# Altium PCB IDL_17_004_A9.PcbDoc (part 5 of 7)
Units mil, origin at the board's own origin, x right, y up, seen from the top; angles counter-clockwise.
Board outline 9493.25 x 7199.68 mil, 6 copper layers (Top Layer - SIG1, Layer 2 - GND1, Layer 3 - PWR1, Layer 4 - PWR2, Layer 5 - GND2, Bottom Layer - SIG2), stack 60.592 mil thick; 403 components, 274 nets, 1834 pads, 1849 vias.
Unrouted connection lines stored in the file: 1.
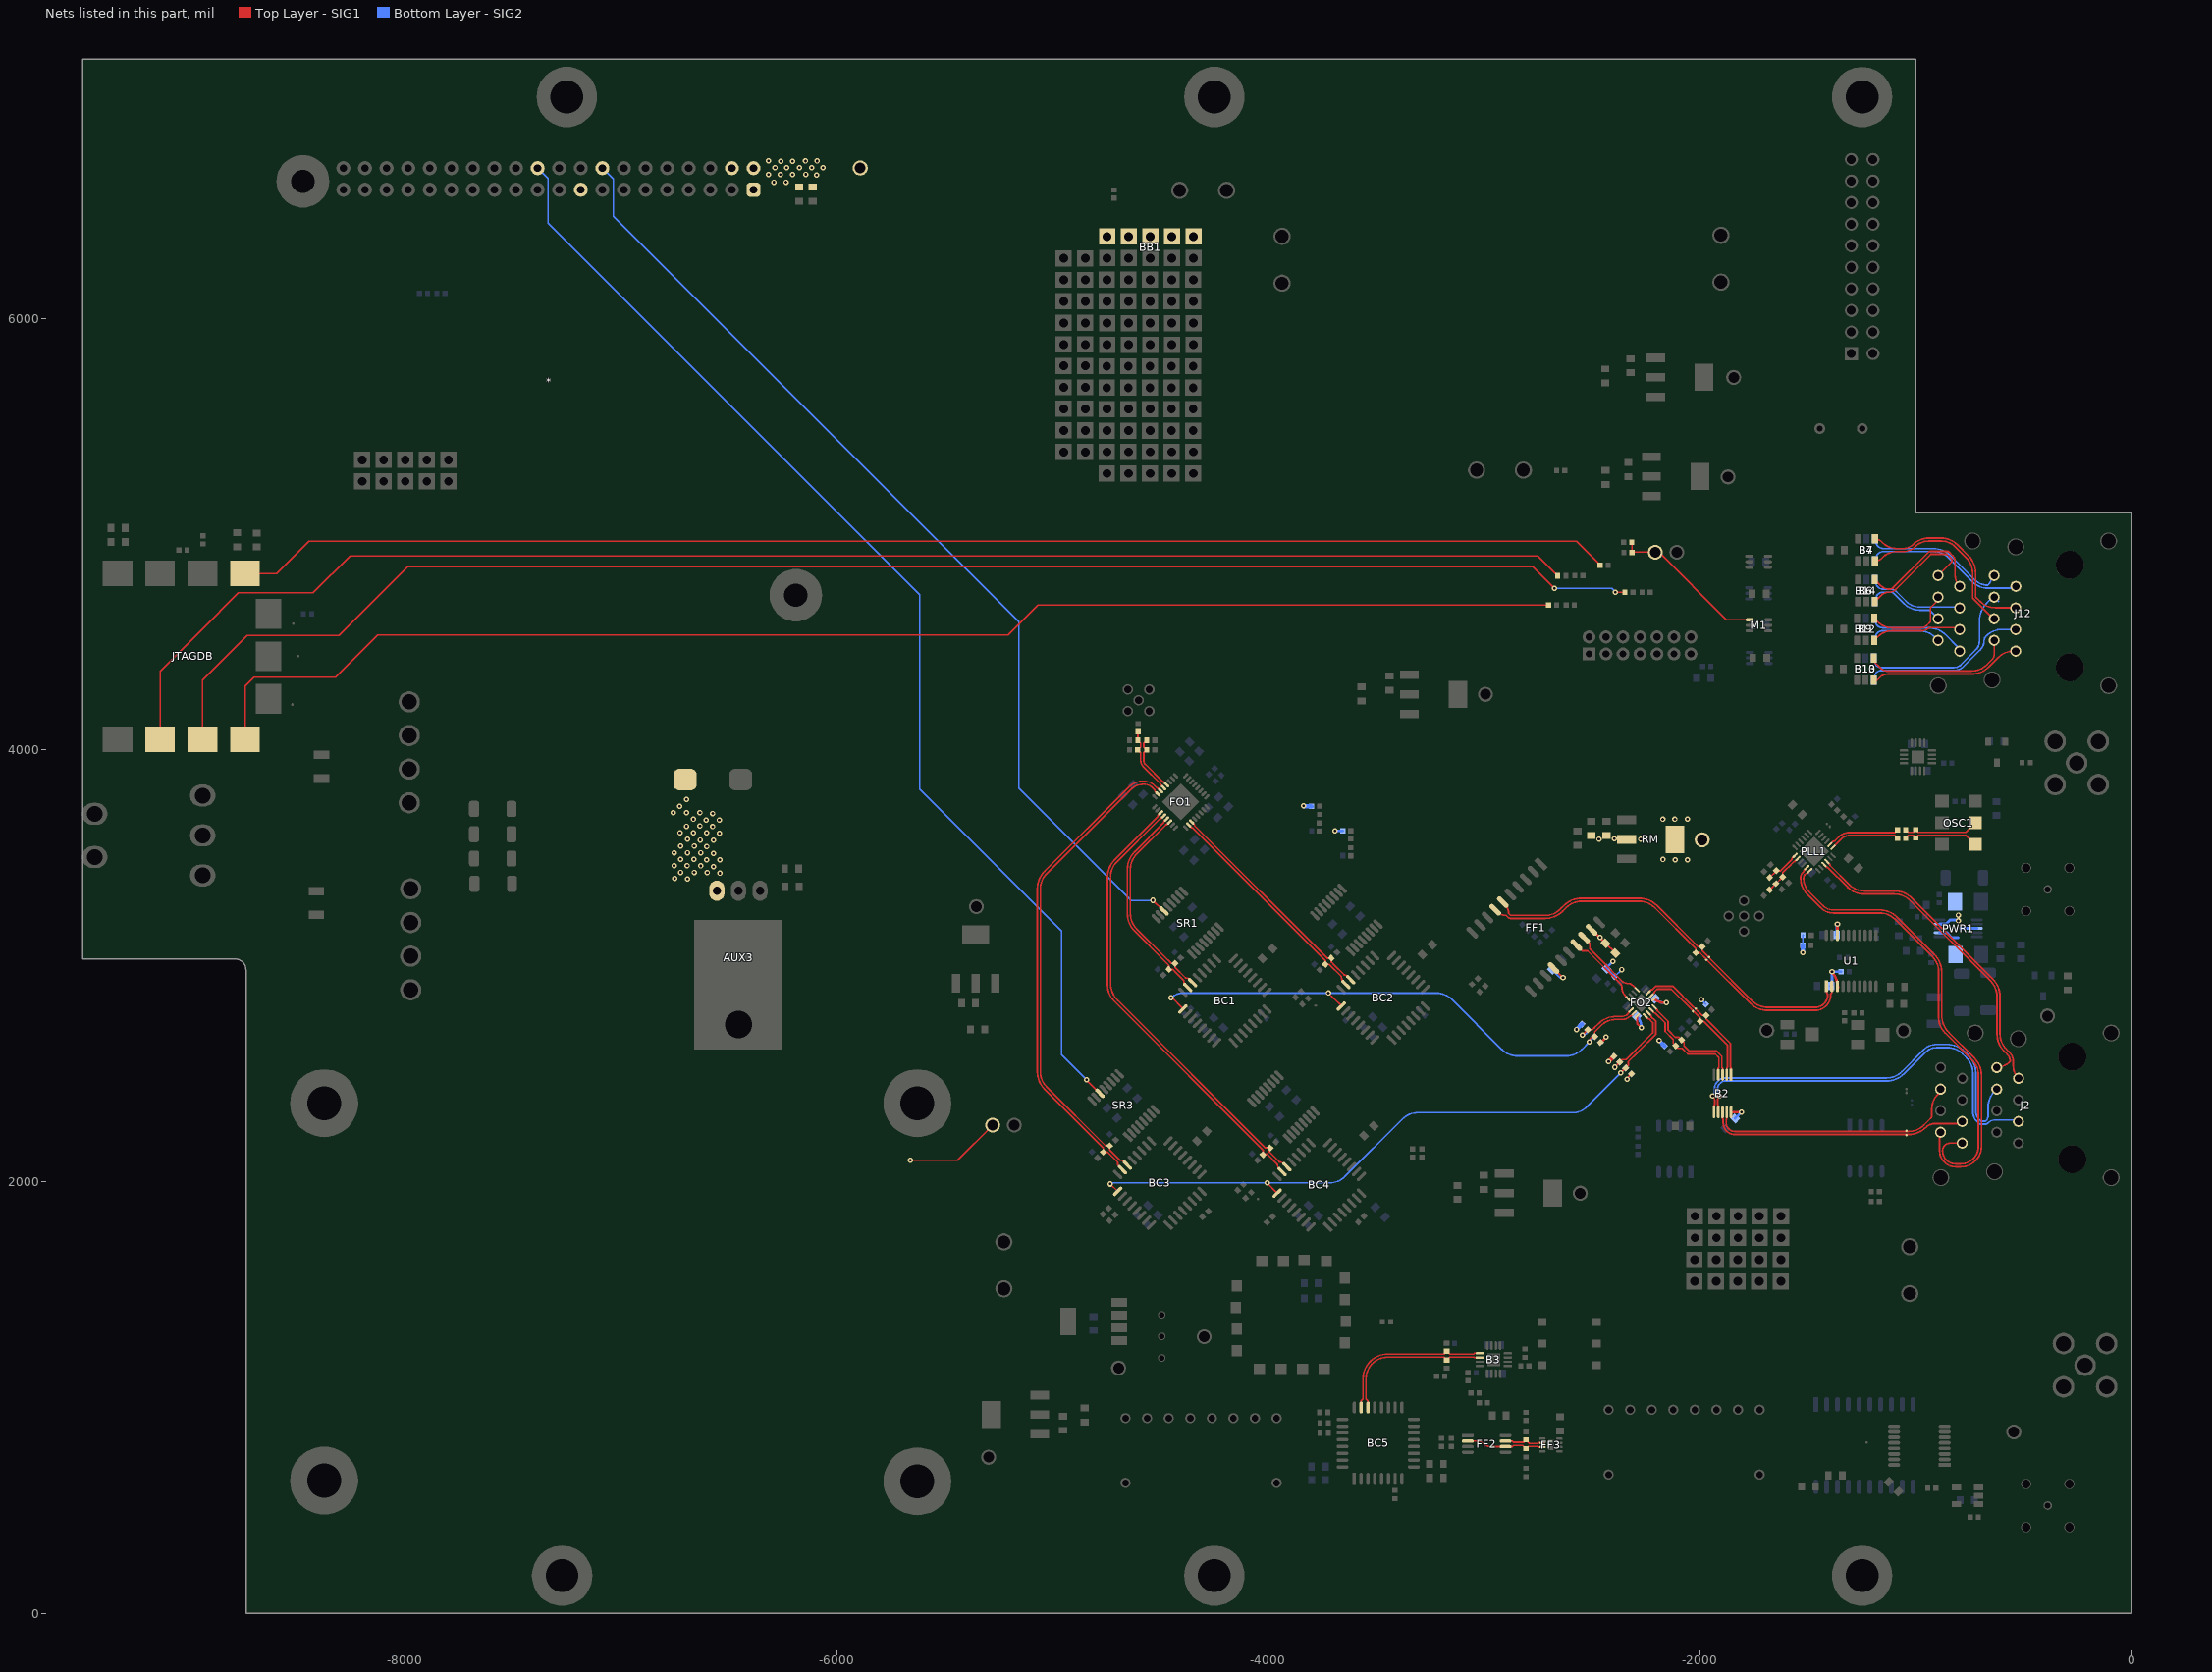
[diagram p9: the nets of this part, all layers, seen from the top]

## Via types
v1: diameter 25, hole 12, Top Layer - SIG1 to Bottom Layer - SIG2, tented both sides, 1502 vias
v2: diameter 25, hole 12, Top Layer - SIG1 to Bottom Layer - SIG2, 184 vias
v3: diameter 25.59, hole 11.81, Top Layer - SIG1 to Bottom Layer - SIG2, tented both sides, 163 vias

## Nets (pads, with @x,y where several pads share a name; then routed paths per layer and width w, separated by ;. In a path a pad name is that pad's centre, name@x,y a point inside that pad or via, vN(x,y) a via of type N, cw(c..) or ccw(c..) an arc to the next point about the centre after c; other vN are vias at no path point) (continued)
RFCLK2-1_N: BC2.23 FO1.26 R60.1 | length 1051.9
  Top Layer - SIG1 w8: FO1.26@-4368.92,3652.85 -4358.33,3642.26 ccw(c-4351.47,3649.12) -4351.47,3639.42 -3736.35,3024.3 R60.1@-3736.35,3007.45 -3718.19,3007.45 -3662.97,2952.24 ccw(c-3623.18,2952.24) -3651.32,2924.1 BC2.23@-3640.66,2913.44
RFCLK2-1_P: BC2.22 FO1.27 R59.1 | length 1051.2
  Top Layer - SIG1 w8: FO1.27@-4355,3666.77 -4344.41,3656.18 cw(c-4351.27,3649.32) -4341.57,3649.32 -3727.9,3035.65 R59.1@-3708.43,3035.65 -3708.43,3017.5 -3695.6,3004.66 -3648.96,2958.03 cw(c-3648.96,2938.08) -3634.86,2952.18 BC2.22@-3618.39,2935.71
RFCLK3-1_N: BC1.23 FO1.21 R58.1 | length 973.2
  Top Layer - SIG1 w8: -4474.75,3016.48 -4461.02,3002.75 R58.1@-4461.02,2983.32 -4443.09,2983.32 -4430.42,2970.65 -4391.82,2932.05 ccw(c-4367.27,2932.05) -4384.63,2914.69 BC1.23@-4369.5,2899.56 ; -4474.76,3016.48 -4619.86,3161.59 cw(c-4539.25,3242.2) -4653.25,3242.2 -4653.25,3447.62 cw(c-4539.25,3447.62) -4619.86,3528.23 -4484.85,3663.24 cw(c-4475.14,3663.24) -4482.01,3670.1 FO1.21@-4471.41,3680.69
RFCLK3-1_P: BC1.22 FO1.22 R57.1 | length 951.2
  Top Layer - SIG1 w8: FO1.22@-4457.49,3666.77 -4468.09,3656.18 cw(c-4474.95,3663.04) -4474.95,3653.34 -4609.96,3518.33 ccw(c-4539.25,3447.62) -4639.25,3447.62 -4639.25,3242.2 ccw(c-4539.25,3242.2) -4609.96,3171.49 -4485.25,3046.77 -4449.51,3011.03 R57.1@-4433.08,3011.03 -4433.08,2993.11 -4384.12,2944.15 cw(c-4384.12,2908.96) -4359.25,2933.85 BC1.22@-4347.23,2921.83
RFCLK4-1_N: BC4.23 FO1.19 R77.1 | length 2103.6
  Top Layer - SIG1 w8: FO1.19@-4499.25,3708.53 -4509.84,3697.94 ccw(c-4502.98,3691.07) -4512.69,3691.07 -4711.86,3491.9 ccw(c-4631.25,3411.29) -4745.25,3411.29 -4745.25,2909.28 ccw(c-4645.25,2909.28) -4715.96,2838.57 -4024.94,2147.55 R77.1@-4024.94,2125.33 -4022.03,2128.24 R77.1@-4021.39,2128.24 ; R77.1@-4020.85,2127.7 R77.1@-4021.39,2128.24 ; BC4.23@-3936.75,2047.06 -3950.32,2060.63 cw(c-3929.2,2081.75) -3959.07,2081.75 -4005.56,2128.24 R77.1@-4021.39,2128.24
RFCLK4-1_P: BC4.22 FO1.20 R76.1 | length 2075.1
  Top Layer - SIG1 w8: -4731.25,3407.27 -4731.25,2920.88 ccw(c-4617.25,2920.88) -4697.86,2840.27 -4014.72,2157.13 R76.1@-3992.5,2157.13 -3994.81,2154.82 -3994.81,2137.29 -3949.17,2091.65 cw(c-3949.17,2061.78) -3928.05,2082.9 BC4.22@-3914.48,2069.33 ; -4731.25,3411.29 cw(c-4631.25,3411.29) -4701.96,3482 -4502.79,3681.17 ccw(c-4502.79,3690.88) -4495.93,3684.02 FO1.20@-4485.33,3694.61
RFCLK5-1_N: BC3.23 FO1.14 R75.1 | length 2282.8
  Top Layer - SIG1 w8: BC3.23@-4675.61,2055.55 -4697.93,2077.87 -4697.93,2090.24 -4744.76,2137.07 R75.1@-4764.71,2137.07 -4764.71,2157.01 -5036.89,2429.19 cw(c-4956.28,2509.8) -5070.28,2509.8 -5070.28,3357.4 cw(c-4956.28,3357.4) -5036.89,3438.01 -4648.83,3826.07 cw(c-4578.12,3755.36) -4578.12,3855.36 -4576.41,3855.36 cw(c-4576.41,3785.83) -4527.25,3835 -4516.71,3824.46 cw(c-4516.71,3814.75) -4509.84,3821.61 FO1.14@-4499.25,3811.02
RFCLK5-1_P: BC3.22 FO1.15 R74.1 | length 2238.6
  Top Layer - SIG1 w8: BC3.22@-4653.34,2077.82 -4675.66,2100.14 -4688.03,2100.14 -4734.87,2146.98 R74.1@-4734.87,2166.91 -4754.81,2166.91 -5026.99,2439.09 cw(c-4956.28,2509.8) -5056.28,2509.8 -5056.28,3357.4 cw(c-4956.28,3357.4) -5026.99,3428.11 -4640.14,3814.96 cw(c-4576.41,3751.24) -4576.41,3841.36 cw(c-4576.41,3785.83) -4537.15,3825.1 -4526.61,3814.56 ccw(c-4516.9,3814.56) -4523.76,3807.69 FO1.15@-4513.17,3797.1
RFCLK6_N: FO1.12 R9.1 R11.2 | length 269.4
  Top Layer - SIG1 w8: R11.2@-4563.89,4044.99 -4577.63,4031.25 -4577.63,4012.92 -4569.71,4004.99 -4567.99,4004.99 R9.1@-4563.99,4000.99 -4577.63,3987.35 -4577.63,3951.99 ccw(c-4551.24,3951.99) -4569.9,3933.33 -4488.87,3852.29 -4484.85,3852.29 FO1.12@-4471.41,3838.86
RFCLK6_P: C22.1 FO1.13 R10.1 R12.2 | length 321.6
  Top Layer - SIG1 w8: R12.2@-4605.28,4000.59 R12.2@-4605.28,4001.15 ; R12.2@-4605.27,4000.59 cw(c-4565.2,4001.15) R12.2@-4605.28,4001.15 ; C22.1@-4604.38,4084.88 -4605.09,4084.16 R10.1@-4605.09,4044.99 -4591.63,4031.53 -4591.63,4012.92 -4599.4,4005.15 -4601.28,4005.15 R12.2@-4605.28,4001.15 ; FO1.13@-4485.33,3824.94 -4498.77,3838.37 -4498.77,3842.39 -4579.8,3923.43 cw(c-4551.24,3951.99) -4591.63,3951.99 -4591.63,3987.51 R12.2@-4605.28,4001.15
RFOUT0_N: J2.8 PLL1.21 | length 1456
  Top Layer - SIG1 w8: PLL1.21@-1426.23,3469.34 -1415.11,3458.22 ccw(c-1408.24,3465.08) -1408.24,3455.38 -1315.98,3363.11 ccw(c-1243.28,3435.81) -1243.28,3333 -1099.42,3333 cw(c-1099.42,3233) -1028.71,3303.71 -654.29,2929.29 cw(c-725,2858.58) -625,2858.58 -625,2684.94 ccw(c-511,2684.94) -591.61,2604.33 -577.25,2589.97 cw(c-610.09,2557.12) -563.64,2557.12 -564.13,2556.63 cw(c-625,2617.49) -625,2531.41 cw(c-628.41,2531.41) J2.8@-626,2529
RFOUT0_P: J2.7 PLL1.22 | length 1480.1
  Top Layer - SIG1 w8: PLL1.22@-1412.31,3483.26 -1401.19,3472.14 cw(c-1408.05,3465.28) -1398.34,3465.28 -1308.92,3375.86 ccw(c-1239.26,3445.52) -1239.26,3347 -1099.42,3347 cw(c-1099.42,3233) -1018.81,3313.61 -644.39,2939.19 cw(c-725,2858.58) -611,2858.58 -611,2684.94 ccw(c-511,2684.94) -581.71,2614.23 -567.35,2599.87 cw(c-610.09,2557.12) -549.64,2557.12 -549.64,2537.02 ccw(c-467.6,2537.02) J2.7@-525.61,2479.01
RFOUT1_N: J2.16 PLL1.17 | length 2145.7
  Top Layer - SIG1 w8: PLL1.17@-1505.57,3455.42 -1516.69,3444.3 ccw(c-1509.83,3437.44) -1519.53,3437.44 -1524.44,3432.53 ccw(c-1500.11,3408.21) -1534.51,3408.21 -1534.51,3403.57 ccw(c-1436.01,3403.57) -1505.67,3333.92 -1440.41,3268.67 ccw(c-1383.28,3325.8) -1383.28,3245 -1168.03,3245 cw(c-1168.03,3145) -1097.32,3215.71 -924.54,3042.93 cw(c-995.25,2972.22) -895.25,2972.22 -895.25,2760.67 ccw(c-795.25,2760.67) -865.96,2689.96 -740.29,2564.29 cw(c-811,2493.58) -711,2493.58 -711,2164 cw(c-792,2164) -792,2083 -816,2083 cw(c-816,2144) -877,2144 cw(c-841.99,2144) -841.99,2179.01 J2.16@-786.01,2179.01
RFOUT1_P: J2.15 PLL1.18 | length 2154.4
  Top Layer - SIG1 w8: PLL1.18@-1491.65,3441.5 -1502.77,3430.38 cw(c-1509.63,3437.24) -1509.63,3427.54 -1514.54,3422.63 ccw(c-1500.11,3408.21) -1520.51,3408.21 -1520.51,3403.57 ccw(c-1436.01,3403.57) -1495.76,3343.82 -1430.51,3278.57 ccw(c-1383.28,3325.8) -1383.28,3259 -1168.03,3259 cw(c-1168.03,3145) -1087.42,3225.61 -914.64,3052.83 ; -914.64,3052.83 cw(c-995.25,2972.22) -881.25,2972.22 -881.25,2772.27 ccw(c-767.25,2772.27) -847.86,2691.66 -730.39,2574.19 cw(c-811,2493.58) -697,2493.58 -697,2164 cw(c-792,2164) -792,2069 -816,2069 cw(c-816,2144) -891,2144 -891,2224 cw(c-886,2224) J2.15@-886,2229
RFOUT2_N: PLL1.13 R13.1 R15.2 | length 161.9
  Top Layer - SIG1 w8: R15.2@-1677.71,3409.84 R13.1@-1647.72,3439.83 ; R13.1@-1647.15,3441.2 cw(c-1649.09,3441.2) R13.1@-1647.72,3439.83 ; PLL1.13@-1561.25,3511.1 -1572.37,3499.98 ccw(c-1565.5,3493.12) -1575.21,3493.12 -1596.89,3471.43 -1597.18,3471.43 -1613.46,3455.16 -1628.78,3439.83 R13.1@-1647.72,3439.83
RFOUT2_P: C23.1 PLL1.14 R14.1 R16.2 | length 202.2
  Top Layer - SIG1 w8: C23.1@-1678.34,3351.98 ccw(c-1678.34,3354.13) -1676.82,3352.61 R16.2@-1648.65,3380.78 -1648.3,3380.78 R14.1@-1617.51,3411.57 -1617.51,3431.3 -1603.56,3445.25 -1591.38,3457.43 -1591.09,3457.43 -1565.31,3483.22 ccw(c-1565.31,3492.92) -1558.45,3486.06 PLL1.14@-1547.33,3497.18
RM_3V3: B2.10 C24.2 C25.2 C26.1 C27.1 C32.2 C33.2 C34.1 C35.2 C36.1 C37.2 C38.1 C39.2 C40.2 C41.2 C108.2 C121.2 FF1.14 FF1.19 FO2.8 FO2.13 L1.1 L2.1 PWR1.2 PWR1.4 PWR1.8 R26.2 R31.2 R32.2 R47.2 R48.2 R49.2 R50.2 RM3V.1 RM.2 RM.4 U1.3 U1.18 | length 1666.7
  Top Layer - SIG1 w6: FF1.14@-2679.41,2989.81 -2635.63,2946.03 v3(-2635.23,2946.03) ; C38.1@-2437.88,3105.4 C36.1@-2393.65,3061.17 ; C36.1@-2393.65,3061.17 cw(c-2394.77,3060.06) C36.1@-2393.19,3060.06 ccw(c-2394.77,3060.06) C36.1@-2393.65,3061.17
  Top Layer - SIG1 w8: v1(-2338,2475.28) -2338,2479.53 R48.2@-2317.86,2499.67
  Top Layer - SIG1 w10: FO2.8@-2291.65,2768.19 -2291.65,2732 v1(-2272.86,2713.21)
  Top Layer - SIG1 w12: FF1.19@-2502.64,3166.59 cw(c-2502.64,3157.99) -2496.55,3164.07 v1(-2464,3131.52) C38.1@-2437.88,3105.4 ; R50.2@-2456.81,2647.57 v1@-2436.65,2667.73 ; FO2.13@-2212.31,2847.53 ccw(c-2166.94,2892.89) -2166.94,2828.74 v1(-2157.33,2828.74) ; B2.10@-1857.1,2323.03 v1@-1809.09,2323.03 ; v3(-1389,2972) -1389,2969 cw(c-1449.07,2908.93) -1364.12,2908.93 U1.3@-1364.12,2905.63 cw(c-1369.14,2900.61) U1.3@-1362.04,2900.61 ; U1.18@-1364.12,3141.85 -1364.12,3192.88 v3(-1364,3193)
  Top Layer - SIG1 w20: v1(-2423.78,2556.62) R47.2@-2399.41,2580.99
  Bottom Layer - SIG2 w6: C34.1@-2686.62,2982.95 -2649.7,2946.03 v3(-2635.23,2946.03) ; v3(-1994.06,2842.36) C39.2@-1973.26,2821.57
  Bottom Layer - SIG2 w8: C40.2@-2396.53,2949.58 -2364.23,2981.88 v1(-2364.23,2983.03) ; R31.2@-1524.32,3095.19 -1524.32,3141.96 cw(c-1523.47,3141.96) R26.2@-1523.47,3142.81
  Bottom Layer - SIG2 w12: v1@-3691.68,3624.64 C25.2@-3655.32,3624.64 ; C121.2@-2433.03,2986.08 C40.2@-2396.53,2949.58 ; C121.2@-2433.03,2986.76 cw(c-2420.99,2986.76) -2429.5,2995.28 v3(-2403.96,3020.82) ; C26.1@-2292.7,2765.06 cw(c-2340.59,2717.16) -2272.86,2717.16 v1(-2272.86,2713.21) ; C108.2@-2208.13,2847.53 ccw(c-2162.77,2892.9) -2162.77,2828.74 v1(-2157.33,2828.74) ; C32.2@-1838.73,2293.87 -1815.21,2317.38 ccw(c-1819.03,2321.2) v1@-1813.63,2321.2 ; C37.2@-1389,2917.99 cw(c-1404.91,2917.99) C37.2@-1393.66,2906.74 -1393.66,2908 -1389,2912.66 v3(-1389,2972) -1388.69,2972.31 R32.2@-1347.02,2972.31 ; C35.2@-1367.66,3143.74 -1367.66,3184.16 cw(c-1355.16,3184.16) v3(-1364,3193) ; -794.86,3174 PWR1.8@-717.81,3174
  Bottom Layer - SIG2 w14: PWR1.2@-891.04,3154.31 -857.31,3154.31 -834,3131 -804,3131 ; PWR1.4@-891.04,3193.68 -861.31,3193.68 -843,3212 v1@-804,3212
  Bottom Layer - SIG2 w20: v1@-3836.47,3740.05 C24.2@-3800.56,3740.05 ; v1@-2572.51,2705.53 R49.2@-2547.94,2730.1 ; v1(-2189.6,2653.67) C41.2@-2165.68,2629.75 ; R31.2@-1524.32,3095.19 -1524.32,3062.01 v3(-1524.19,3061.87)
  other v1: -1809.15,2322.64 -2435.65,2670.14 -2572.58,2705.53 -804.43,3208.31 -804.43,3235.31 -2115.43,3491.08 -2059.56,3491.78 -2171.99,3492.49 -2468.98,3587.24 -2275.94,3586.54 -2398.27,3588.66 -3692.13,3625.09 -2173.41,3679.17 -2116.84,3679.17 -2058.15,3679.88 -3836.51,3741.09
RMOUT0_N: B2.8 J2.14 TP10.1 | length 1201.8
  Top Layer - SIG1 w8: B2.8@-1896.47,2322.07 -1896.47,2294.53 ccw(c-1886.77,2294.53) -1893.63,2287.66 -1893.63,2272.63 ccw(c-1840,2272.63) -1840,2219 -1034.42,2219 ccw(c-1034.42,2333) -953.81,2252.39 cw(c-913.7,2212.27) -913.7,2269.01 J2.14@-786.01,2269.01
RMOUT0_P: B2.9 J2.11 TP9.1 | length 1163.9
  Top Layer - SIG1 w8: B2.9@-1876.79,2322.07 -1876.79,2294.53 cw(c-1886.49,2294.53) -1879.63,2287.66 -1879.63,2272.63 ccw(c-1840,2272.63) -1840,2233 -1034.42,2233 ccw(c-1034.42,2333) -963.71,2262.29 -932,2294 ccw(c-944.07,2306.07) -927,2306.07 -927,2336.58 cw(c-827,2336.58) J2.11@-897.71,2407.29
RMOUT1_N: B2.6 J2.6 | length 1920.8
  Top Layer - SIG1 w8: v3(-1941.8,2396.77) -1939.28,2394.25 cw(c-1954.44,2379.09) -1933,2379.09 -1933,2356.47 ccw(c-1926.14,2349.6) -1935.84,2349.6 B2.6@-1935.84,2322.07
  Bottom Layer - SIG2 w8: v3(-1941.8,2396.77) ccw(c-1963.03,2418) -1933,2418 -1933,2434.07 cw(c-1894.76,2434.07) -1921.8,2461.11 -1915.24,2467.67 ; -1915.23,2467.68 cw(c-1883.62,2436.04) -1883.62,2480.77 -1136.65,2480.77 ccw(c-1136.65,2580.77) -1065.94,2510.06 -964.34,2611.66 cw(c-905.41,2552.73) -905.41,2636.07 -855.45,2636.07 cw(c-855.45,2522.07) -774.84,2602.68 -756.27,2584.11 cw(c-836.88,2503.5) -722.88,2503.5 -722.88,2325.61 ccw(c-670.71,2325.61) -707.6,2288.72 -699.52,2280.64 -680.08,2280.64 ccw(c-680.08,2286.32) -676.07,2282.31 ccw(c-700.08,2306.32) -666.12,2306.32 -666.12,2347.46 cw(c-566.12,2347.46) -636.83,2418.17 J2.6@-626,2429 cw(c-626,2457.97) J2.6@-646.49,2437.49
RMOUT1_P: B2.7 J2.3 | length 1886.6
  Top Layer - SIG1 w8: B2.7@-1916.16,2322.07 -1916.16,2349.61 ccw(c-1925.86,2349.61) -1919,2356.47 -1919,2379.09 cw(c-1897.56,2379.09) -1912.72,2394.25 v3(-1910.2,2396.77)
  Bottom Layer - SIG2 w8: v3(-1910.2,2396.77) cw(c-1888.97,2418) -1919,2418 -1919,2434.07 cw(c-1894.76,2434.07) -1911.9,2451.21 -1905.34,2457.77 cw(c-1883.62,2436.04) -1883.62,2466.77 -1136.65,2466.77 ccw(c-1136.65,2580.77) -1056.04,2500.16 -954.14,2602.06 ; -953.65,2601.59 cw(c-905.82,2553.74) -905.82,2621.4 -854.78,2621.4 cw(c-854.78,2521.4) -784.07,2592.11 -766.17,2574.21 cw(c-836.88,2503.5) -736.88,2503.5 -736.88,2325.61 ccw(c-670.71,2325.61) -717.5,2278.82 -709.42,2270.74 ccw(c-699.52,2280.64) -699.52,2266.64 -677.73,2266.64 ccw(c-677.73,2280.64) -667.83,2270.74 ; J2.3@-535.58,2288.58 J2.3@-526.01,2279.01 ccw(c-543.56,2261.45) -543.56,2286.28 -632.67,2286.28 ccw(c-632.67,2238.91) -666.17,2272.41 ; -667.83,2270.74 -666.17,2272.41 ; -667.83,2270.74 -666.17,2272.41
RPI_3V3: *.1 *.17
RPI_5V: *.2 *.4 AUX3.3 BB1.1 BB1.2 BB1.3 BB1.4 BB1.5 C86.1 C87.1 C117.1 J14.2 RPI_5V.1 | length 449.1
  Top Layer - SIG1 w8: v1@-5659.11,2099.9 -5439.68,2099.9 J14.2@-5277.3,2262.28
  other v1: -5658.81,2100.24 -6691.19,3402.23 -6750.19,3405.23 -6540,3429 -6599,3432 -6722.19,3433.23 -6660,3433 -6571,3460 -6692.19,3463.23 -6630,3463 -6753.19,3464.23 -6602,3491 -6540,3491 -6722.19,3493.23 -6661,3494 -6570.19,3521.23 -6753.19,3524.23 -6691.19,3524.23 -6629.19,3524.23 -6601.19,3552.23 -6723.19,3554.23 -6660.19,3555.23 -6571.19,3582.23 -6632.19,3583.23 -6691.19,3586.23 -6543,3614 -6726,3617 -6664,3617 -6602,3617 -6574,3645 -6696,3647 -6633,3648 -6544,3675 -6605,3676 -6664,3679 -6574,3706 -6757,3709 -6695,3709 -6633,3709 -6727,3739 -6695,3771 -6290.5,6630.43 -6234.78,6630.46 -6092.31,6663.95 -6316.18,6666.16 -6260.46,6666.19 -6203.66,6666.56 -6142.65,6666.75 -6285.18,6697.16 -6172.98,6697.11 -6231.51,6697.7 -6116.18,6697.47 -6062.63,6697.47 -6204.63,6727.09 -6258.9,6727.87 -6315.69,6728.66 -6144.03,6728.61 -6090.48,6728.61
RVM2_N: FF1.7 R28.2 TP5.1 U1.2 | length 1885.7
  Top Layer - SIG1 w8: FF1.7@-2949.45,3259.85 -2940.96,3251.36 ccw(c-2897.5,3294.82) -2897.5,3233.36 -2888.31,3224.16 ccw(c-2878.41,3234.06) -2878.41,3220.06 -2717.61,3220.06 ccw(c-2717.61,3334.06) -2637,3253.45 -2620.72,3269.74 cw(c-2550.01,3199.03) -2550.01,3299.03 -2280.94,3299.03 cw(c-2280.94,3199.03) -2210.23,3269.74 -2019.7,3079.21 R28.2@-2019.7,3060.47 -2000.96,3060.47 -1972.59,3032.1 TP5.1@-1972.59,3027.2 ; TP5.1@-1969.65,3029.16 -1969.65,3028.65 -1768.22,2827.22 ccw(c-1687.61,2907.83) -1687.61,2793.83 -1466.25,2793.83 ccw(c-1466.25,2864.57) -1395.5,2864.57 -1395.5,2869.26 ccw(c-1409.49,2883.25) -1389.71,2883.25 U1.2@-1389.71,2905.63
RVM2_P: FF1.6 R29.2 TP4.1 U1.1 | length 1854.8
  Top Layer - SIG1 w8: FF1.6@-2914.1,3295.21 -2905.6,3286.71 cw(c-2949.06,3243.26) -2887.6,3243.26 -2878.41,3234.06 -2717.61,3234.06 ccw(c-2717.61,3334.06) -2646.9,3263.35 -2630.62,3279.64 cw(c-2550.01,3199.03) -2550.01,3313.03 -2280.94,3313.03 cw(c-2280.94,3199.03) -2200.33,3279.64 -2009.8,3089.11 R29.2@-1991.06,3089.11 -1991.06,3070.37 TP4.1@-1961.53,3040.85 ; TP4.1@-1958.72,3040.85 TP4.1@-1961.53,3040.85 ; U1.1@-1415.3,2905.63 -1415.3,2883.25 ccw(c-1395.51,2883.25) -1409.5,2869.26 -1409.5,2864.57 cw(c-1466.25,2864.57) -1466.25,2807.83 -1687.61,2807.83 cw(c-1687.61,2907.83) -1758.32,2837.12 -1953.01,3031.81 -1953.01,3032.32 TP4.1@-1961.53,3040.85
RVM_FO0-1_N: B2.2 FO2.14 R41.1 TP8.1 | length 623.3
  Top Layer - SIG1 w8: FO2.14@-2226.23,2861.45 -2212.26,2875.41 -2212.26,2879.43 -2199.57,2892.13 -2133.35,2892.13 -2022.87,2781.65 -2022.87,2781.39 -2022.6,2781.38 -2000.3,2759.08 R41.1@-2000.3,2742.95 -1983.7,2742.95 -1873.95,2633.19 -1873.95,2529.7 -1876.79,2526.85 B2.2@-1876.79,2495.29
RVM_FO0-1_P: B2.1 FO2.15 R42.1 TP7.1 | length 664.9
  Top Layer - SIG1 w8: FO2.15@-2240.15,2875.37 -2226.18,2889.33 -2222.16,2889.33 -2211.85,2899.65 -2205.37,2906.13 -2127.55,2906.13 -2030.77,2809.35 -2030.33,2809.35 -1991.23,2770.25 R42.1@-1972.85,2770.25 ; R42.1@-1978.51,2770.25 R42.1@-1972.85,2770.25 ; B2.1@-1857.1,2495.29 -1857.1,2526.85 -1859.95,2529.7 -1859.95,2640.74 -1972.85,2753.65 R42.1@-1972.85,2770.25
RVM_FO1-1_N: B2.4 FO2.11 R45.2 | length 518.3
  Top Layer - SIG1 w8: FO2.11@-2226.23,2796.03 -2212.26,2782.06 -2208.24,2782.06 -2162.23,2736.05 -2162.23,2696.64 -2124.6,2659.01 -2124.6,2641.98 R45.2@-2112.86,2630.24 -2101.12,2618.5 -2084.09,2618.5 -2057.41,2591.83 -1930.25,2591.83 -1913.32,2574.9 -1913.32,2529.7 -1916.16,2526.85 B2.4@-1916.16,2495.29
RVM_FO1-1_P: B2.3 FO2.12 R44.2 | length 529.9
  Top Layer - SIG1 w8: FO2.12@-2212.31,2809.95 -2198.34,2795.98 -2198.34,2791.96 -2148.23,2741.85 -2148.23,2702.44 -2114.94,2669.15 -2097.9,2669.15 R44.2@-2086.16,2657.41 -2074.43,2645.68 -2074.43,2628.64 -2051.61,2605.83 -1924.45,2605.83 -1899.32,2580.7 -1899.32,2529.7 -1896.47,2526.85 B2.3@-1896.47,2495.29
RVM_FO2_N: FO2.9 R47.1 R51.2 | length 376.9
  Top Layer - SIG1 w8: v3(-2395.57,2530.7) -2372.69,2553.58 R47.1@-2372.69,2554.27 ; R47.1@-2367.03,2554.27 R47.1@-2372.69,2554.27 ; FO2.9@-2254.07,2768.19 -2242.94,2757.07 ccw(c-2236.08,2763.93) -2236.08,2754.22 -2219.06,2737.2 -2219.06,2690.2 -2276.23,2633.03 -2299.05,2610.2 -2299.05,2609.81 -2342.86,2566 -2360.95,2566 R47.1@-2372.69,2554.27
  Bottom Layer - SIG2 w8: v3(-2395.57,2530.7) -2372.8,2553.47 R51.2@-2372.8,2554.82
RVM_FO2_P: BC3.25 BC4.25 FO2.10 R48.1 R52.2 | length 3077.8
  Top Layer - SIG1 w8: v3(-4732.37,1989.56) -4732.11,1989.56 BC3.25@-4697.88,1955.33 ; v3(-4005.67,1994.83) -4006.34,1994.83 -3959.5,1947.99 cw(c-3960.64,1946.84) BC4.25@-3959.02,1946.84 ; v3(-2367.33,2503.65) R48.1@-2344.59,2526.39 -2332.85,2538.13 -2332.85,2556.21 -2289.15,2599.91 -2285.05,2604.01 -2285.05,2604.4 -2205.06,2684.4 -2205.06,2743 -2209.16,2747.1 -2226.18,2764.12 ccw(c-2235.89,2764.12) FO2.10@-2229.02,2770.98 ; FO2.10@-2240.15,2782.11 FO2.10@-2229.02,2770.99
  Bottom Layer - SIG2 w8: v3(-4732.37,1989.56) cw(c-4719.65,1976.84) -4719.65,1994.83 v3(-4005.67,1994.83) -3715.91,1994.83 ccw(c-3715.91,2094.83) -3645.19,2024.12 -3378.82,2290.49 cw(c-3308.11,2219.77) -3308.11,2319.77 -2592.63,2319.77 ccw(c-2592.63,2419.77) -2521.91,2349.06 v3(-2367.33,2503.65) ; v3@-2364.03,2506.95 v3(-2367.33,2503.65) ; R52.2@-2344.59,2526.39 v3(-2367.33,2503.65)
RVM_FO3_N: FO2.6 R49.1 R53.2 | length 307.6
  Top Layer - SIG1 w8: v1(-2545.32,2679.41) -2545.32,2679.74 R53.2@-2520.85,2704.21 -2498.62,2704.21 -2490,2712.83 -2470.15,2732.73 cw(c-2390.24,2652.82) -2390.24,2765.83 -2362.94,2765.83 ccw(c-2362.94,2807.53) -2333.45,2778.04 cw(c-2323.75,2778.04) -2330.61,2784.91 FO2.6@-2319.49,2796.03
  Bottom Layer - SIG2 w8: R49.1@-2521.21,2703.38 cw(c-2545.18,2703.38) v1@-2545.18,2679.41 ; v1@-2545.18,2679.41 v1(-2545.32,2679.41) v1@-2545.18,2679.41
RVM_FO3_P: BC1.25 BC2.25 FO2.7 R50.1 R54.2 | length 2577.2
  Top Layer - SIG1 w8: v1(-4450.54,2851.86) -4445.23,2851.86 -4397.97,2804.59 cw(c-4402.52,2800.03) BC1.25@-4396.08,2800.03 ; v1(-3721.99,2873.9) -3696.49,2848.41 cw(c-3696.49,2846.03) -3694.81,2847.71 -3660.32,2813.22 BC2.25@-3662.93,2813.22 ; v1@-2513.22,2647.59 v1(-2513.5,2647.59) cw(c-2488.9,2647.59) -2488.9,2672.19 R50.1@-2488.61,2672.19 ; R50.1@-2483.36,2674.37 cw(c-2488.61,2679.62) R50.1@-2488.61,2672.19 ; FO2.7@-2305.57,2782.11 -2316.69,2770.99 cw(c-2323.55,2777.85) -2323.55,2768.14 cw(c-2362.94,2807.53) -2362.94,2751.83 -2390.24,2751.83 ccw(c-2390.24,2652.82) -2460.25,2722.83 -2476,2707.08 -2488.61,2694.42 R50.1@-2488.61,2672.19
  Bottom Layer - SIG2 w8: v1(-4450.54,2851.86) cw(c-4397.32,2798.64) -4397.32,2873.9 v1(-3721.99,2873.9) -3220.92,2873.9 cw(c-3220.92,2773.9) -3150.21,2844.61 -2917.71,2612.12 ccw(c-2847,2682.83) -2847,2582.83 -2619.68,2582.83 ccw(c-2619.68,2682.83) -2548.97,2612.12 v1(-2513.5,2647.59) ; v1@-2522.52,2647.59 v1(-2513.5,2647.59) ; v1@-2522.34,2643.93 cw(c-2513.5,2635.09) v1(-2513.5,2647.59) ; R54.2@-2488.9,2672.19 v1(-2513.5,2647.59)
SCROD_SEL: J13.1 M1.4 R117.1 R118.1 | length 721.6
  Top Layer - SIG1 w6: R118.1@-2316.26,4961.95 -2315.94,4961.64 R117.1@-2315.94,4915.31 -2315.26,4916 J13.1@-2208,4916 -2191.19,4916 -1878.31,4603.12 M1.4@-1770.98,4603.12
SR_A: *.16 SR1.14 | length 4578.4
  Top Layer - SIG1 w6: v3(-4534.61,3303.57) -4487.09,3256.05 ccw(c-4483.64,3259.51) SR1.14@-4483.64,3254.62
  Bottom Layer - SIG2 w6: *.16@-7085.12,6695.35 -7035,6645.23 -7035,6473 -5156,4594 -5156,3824 -4635.57,3303.57 v3(-4534.61,3303.57)
SR_B: *.22 SR3.14 | length 5379
  Top Layer - SIG1 w6: v3(-4842,2472) -4842,2471 SR3.14@-4780.61,2409.61
  Bottom Layer - SIG2 w6: *.22@-7385.12,6695.35 *.22@-7370.65,6695.35 ; -7336.61,6646.84 -7336.61,6439.61 -5616,4719 -5616,3819 -4958,3161 -4958,2588 v3(-4842,2472)
  Bottom Layer - SIG2 w8: *.22@-7385.12,6695.35 -7336.61,6646.84
SYNC_RM_N: FF1.17 FO2.4 | length 371.1
  Top Layer - SIG1 w8: FF1.17@-2564.86,3087.39 FF1.17@-2573.35,3095.88 -2546.86,3069.39 -2521.4,3069.39 -2369.54,2917.53 cw(c-2386.15,2900.92) -2362.66,2900.92 ccw(c-2304.39,2900.92) -2345.59,2859.72 FO2.4@-2333.41,2847.53
SYNC_RM_P: FF1.18 FO2.1 | length 370.4
  Top Layer - SIG1 w8: FF1.18@-2529.5,3122.74 FF1.18@-2537.99,3131.24 -2511.5,3104.74 -2511.5,3079.29 -2474.84,3042.63 -2362.33,2930.12 ccw(c-2334.38,2958.08) -2334.38,2918.54 cw(c-2334.38,2886.01) -2311.37,2909.01 FO2.1@-2291.65,2889.29
TCK: JTAGDB.2 R114.2 | length 7048.6
  Top Layer - SIG1 w6: JTAGDB.2@-9134.15,4050 -9134.15,4363.93 -8945.27,4552.81 -8770.87,4727.22 -8425.56,4727.22 -8253.58,4899.19 -2753.25,4899.19 -2751.2,4897.15 R114.2@-2659.9,4805.84
TCK1_N: B7.3 J12.8 | length 654.7
  Bottom Layer - SIG2 w8: B7.3@-1190,4977.44 cw(c-1199.66,4967.78) -1186,4967.78 ccw(c-1151.48,4967.78) -1151.48,4933.26 -920,4933.26 cw(c-920,4819.26) -839.39,4899.87 -727.97,4788.45 ccw(c-667.61,4848.8) -667.61,4763.45 -665.07,4765.99 ccw(c-701.53,4802.45) J12.8@-649.97,4802.45
TCK1_P: B7.4 J12.7 | length 729.4
  Bottom Layer - SIG2 w8: B7.4@-1190,4875.08 ccw(c-1199.66,4884.73) -1186,4884.73 cw(c-1151.48,4884.73) -1151.48,4919.26 -920,4919.26 cw(c-920,4819.26) -849.29,4889.97 -737.87,4778.55 ccw(c-667.61,4848.8) -667.61,4749.45 -556.84,4749.45 ccw(c-556.84,4759.71) J12.7@-549.58,4752.46
TCK2_N: B9.3 J12.16 | length 482.3
  Bottom Layer - SIG2 w8: B9.3@-1193.63,4610.18 cw(c-1203.29,4600.52) -1189.63,4600.52 ccw(c-1155.11,4600.52) -1155.11,4566 -942.22,4566 cw(c-942.22,4452) -861.61,4532.61 -805.78,4476.78 cw(c-824.56,4458.01) J12.16@-798.01,4458.34 ; J12.16@-786.01,4467.01 J12.16@-798.01,4458.34 ; J12.16@-798.01,4458.34 cw(c-824.56,4458.01) J12.16@-798.01,4458.01 J12.16@-798.01,4458.34
TCK2_P: B9.4 J12.15 | length 336.1
  Bottom Layer - SIG2 w8: B9.4@-1193.63,4507.82 ccw(c-1203.29,4517.48) -1189.63,4517.48 cw(c-1155.11,4517.48) -1155.11,4552 -983.42,4552 cw(c-983.42,4452) -912.71,4522.71 J12.15@-898,4508 J12.15@-897.92,4508.08
TDI: JTAGDB.3 R116.2 | length 7129
  Top Layer - SIG1 w6: JTAGDB.3@-8937.3,4050 -8937.3,4323.59 -8827.95,4432.95 -8731.31,4529.58 -8306.18,4529.58 -7987.71,4848.06 -6134.58,4848.06 -6134.16,4848.47 -2775.47,4848.47 v3(-2675,4748) ; v3(-2392.5,4731.14) -2352.71,4731.14 -2351.55,4732.29 R116.2@-2349.39,4730.14
  Bottom Layer - SIG2 w6: v3(-2675,4748) -2409.53,4748 -2392.58,4731.05 v3(-2392.5,4731.14)
TDI1_N: B10.3 J12.6 | length 836.3
  Bottom Layer - SIG2 w8: B10.3@-1195.03,4425.99 cw(c-1204.69,4416.33) -1191.03,4416.33 -1191.03,4409.84 ccw(c-1163,4409.84) -1163,4381.81 -823.89,4381.81 ccw(c-823.89,4426.95) -791.97,4395.03 -723,4464 ccw(c-764.04,4505.04) -706,4505.04 -706,4599.2 cw(c-592,4599.2) -672.61,4679.81 -649.97,4702.45 J12.6@-640.26,4692.74 ; J12.6@-638,4708 -618.28,4688.28
TDI1_P: B10.4 J12.3 | length 775.2
  Bottom Layer - SIG2 w8: B10.4@-1195.03,4323.63 ccw(c-1204.69,4333.29) -1191.03,4333.29 -1191.03,4339.78 cw(c-1163,4339.78) -1163,4367.81 -823.89,4367.81 ccw(c-823.89,4426.95) -782.07,4385.13 -713.1,4454.1 ; -712.71,4454.1 -701.4,4465.42 ccw(c-740.98,4505) -685,4505 cw(c-653.62,4505) -675.81,4527.19 -674.28,4528.72 cw(c-603.57,4458.01) -603.57,4558.01 J12.3@-538.01,4558.01
TDI2_N: B12.3 J12.14 | length 418.3
  Top Layer - SIG1 w8: B12.3@-1193.63,4507.82 -1175.23,4526.22 cw(c-1113,4463.99) -1113,4552 -976.56,4552 ccw(c-976.56,4603.56) -940.1,4567.1 -807.1,4567.1 J12.14@-798.01,4558.01 J12.14@-798.01,4558.34
TDI2_P: B12.4 J12.11 | length 413.6
  Top Layer - SIG1 w8: B12.4@-1193.63,4610.18 -1175.23,4591.78 ccw(c-1113,4654.01) -1113,4566 -976.56,4566 ccw(c-976.56,4603.56) -950,4577 -933.59,4593.41 -933.59,4659 -898,4694.59 J12.11@-898,4708
TDO: JTAGDB.8 R115.2 | length 6442.2
  Top Layer - SIG1 w6: JTAGDB.8@-8740.45,4817.72 -8594.28,4817.72 -8444.41,4967.59 -2573.38,4967.59 R115.2@-2460.79,4855 ; JTAGDB.8@-8738.8,4773.93 JTAGDB.8@-8738.8,4827.77
TDO1_N: B13.4 J12.2 | length 673.5
  Top Layer - SIG1 w8: B13.4@-1195.63,4410.18 -1165.57,4380.12 ccw(c-1130.85,4414.84) -1130.85,4365.74 -742.68,4365.74 ccw(c-742.68,4465.74) -671.97,4395.03 -647,4420 ccw(c-668.73,4441.73) -638,4441.73 J12.2@-638,4508
TDO1_P: B13.3 J12.1 | length 717.2
  Top Layer - SIG1 w8: B13.3@-1195.63,4307.82 -1166.45,4337 cw(c-1130.85,4301.4) -1130.85,4351.74 -742.68,4351.74 ccw(c-742.68,4465.74) -662.07,4385.13 -618.48,4428.72 cw(c-547.77,4358.01) -547.77,4458.01 J12.1@-538.01,4458.01 ; J12.1@-558.7,4452.46 J12.1@-549.97,4452.46
TDO2_N: B14.4 J12.10 | length 606.3
  Top Layer - SIG1 w8: B14.4@-1190.63,4789.18 -1162.33,4760.88 ccw(c-1124,4799.21) -1124,4745 ccw(c-1124,4771.55) -1105.22,4752.78 -941.95,4916.05 cw(c-930,4904.1) -930,4921 -857,4921 cw(c-857,4907) -847.11,4916.91 -829.91,4899.71 cw(c-855.72,4873.9) -819.22,4873.9 -819.22,4810.17 ccw(c-745.45,4810.17) J12.10@-797.61,4758.01
TDO2_P: B14.3 J12.9 | length 555.2
  Top Layer - SIG1 w8: B14.3@-1190.63,4686.82 -1162.33,4715.12 cw(c-1124,4676.79) -1124,4731 ccw(c-1124,4771.55) -1095.32,4742.88 -932.05,4906.15 cw(c-930,4904.1) -930,4907 -857,4907 -839.81,4889.81 cw(c-855.72,4873.9) -833.22,4873.9 cw(c-835.92,4873.9) -834.01,4871.99 J12.9@-898,4808
"TEST RF CLK-1_N": B3.9 BC5.23 R95.1 | length 755
  Top Layer - SIG1 w8: BC5.23@-3570.48,954.49 -3570.48,986.05 -3561.74,994.8 -3561.74,1087.39 cw(c-3447.74,1087.39) -3447.74,1201.39 -3187.52,1201.39 R95.1@-3174.12,1214.79 -3160.73,1201.39 -3049.16,1201.39 -3045.12,1205.43 B3.9@-3021.12,1205.43
"TEST RF CLK-1_P": B3.10 BC5.22 R94.1 | length 752
  Top Layer - SIG1 w8: BC5.22@-3538.99,954.49 -3538.99,986.05 -3547.74,994.8 -3547.74,1087.39 cw(c-3447.74,1087.39) -3447.74,1187.39 -3187.52,1187.39 R94.1@-3174.12,1174 -3160.73,1187.39 -3046.77,1187.39 -3045.12,1185.75 B3.10@-3021.12,1185.75 B3.10@-3041.1,1185.75
"TEST RF CLK-2_N": FF2.2 FF2.6 FF3.3 R103.1 | length 373.2
  Top Layer - SIG1 w8: FF2.2@-3076.77,798.48 -3034.2,798.48 cw(c-3034.2,748.98) -2999.21,783.98 ccw(c-2972.42,810.76) -2972.42,772.89 FF2.6@-2901.58,772.89 -2870.02,772.89 -2864.22,778.68 -2821.7,778.68 R103.1@-2806.21,763.19 ; R103.1@-2800.4,763.19 R103.1@-2806.21,763.19 ; FF3.3@-2730.58,770.82 -2749.34,770.82 -2752.18,773.67 -2795.73,773.67 R103.1@-2806.21,763.19
"TEST RF CLK-2_P": FF2.7 FF3.2 R104.1 | length 186.6
  Top Layer - SIG1 w8: FF2.7@-2901.58,798.48 -2870.02,798.48 -2864.22,792.68 -2818.5,792.68 R104.1@-2807.21,803.97 ; R104.1@-2806.58,803.97 R104.1@-2807.21,803.97 ; FF3.2@-2730.58,790.51 -2749.34,790.51 -2752.18,787.67 -2790.9,787.67 R104.1@-2807.21,803.97
TMS: JTAGDB.4 R113.2 | length 6439.5
  Top Layer - SIG1 w6: JTAGDB.4@-8740.45,4050 -8740.45,4111.5 -8740.45,4296.42 -8699.62,4337.24 -8321.11,4337.24 -8124.94,4533.41 -5206.59,4533.41 -5068,4672 R113.2@-2702.94,4672
TMS1_N: B4.3 J12.4 | length 806.5
  Top Layer - SIG1 w8: B4.3@-1190,4875.08 ccw(c-1190,4918) -1159.65,4887.65 -1157.33,4889.97 cw(c-1086.62,4819.26) -1086.62,4919.26 -1059.25,4919.26 ccw(c-1059.25,4997.25) -1004.1,4942.1 cw(c-941.57,4879.57) -941.57,4968 -882,4968 cw(c-882,4878.67) -818.84,4941.84 -767.26,4890.26 cw(c-837.97,4819.55) -737.97,4819.55 -737.97,4708.45 ccw(c-723.97,4708.45) -733.88,4698.56 ; -733.87,4698.55 -658.6,4623.28 cw(c-679.42,4602.45) J12.4@-649.97,4602.45
TMS1_P: B4.4 J12.5 | length 879.8
  Top Layer - SIG1 w8: B4.4@-1190,4977.44 cw(c-1190,4934.52) -1159.65,4964.87 -1157.33,4962.55 ccw(c-1086.62,5033.26) -1086.62,4933.26 -1059.25,4933.26 ccw(c-1059.25,4997.25) -1014,4952 cw(c-941.57,4879.57) -941.57,4982 -882,4982 cw(c-882,4878.67) -808.94,4951.74 -757.36,4900.16 cw(c-837.97,4819.55) -723.97,4819.55 -723.97,4708.45 -704.26,4688.74 ccw(c-633.55,4759.45) -633.55,4659.45 -566.86,4659.45 cw(c-566.86,4635.57) J12.5@-549.97,4652.46
TMS2_N: B6.3 J12.12 | length 449.6
  Bottom Layer - SIG2 w8: B6.3@-1190.63,4789.18 cw(c-1200.29,4779.52) -1186.63,4779.52 ccw(c-1152.11,4779.52) -1152.11,4745 -1118,4745 cw(c-1118,4706.86) -1091.03,4733.83 -1045.51,4688.31 ccw(c-982,4751.81) -982,4662 -802,4662 J12.12@-798.01,4658.01
TMS2_P: B6.4 J12.13 | length 364.5
  Bottom Layer - SIG2 w8: B6.4@-1190.63,4686.82 ccw(c-1200.29,4696.48) -1186.63,4696.48 cw(c-1152.11,4696.48) -1152.11,4731 -1118,4731 cw(c-1118,4706.86) -1100.93,4723.93 -1055.41,4678.41 ccw(c-982,4751.81) -982,4648 -938,4648 J12.13@-898,4608
VCO1-1_N: C10.2 PLL1.2 | length 337.8
  Top Layer - SIG1 w8: PLL1.2@-1398.39,3562.6 -1384.42,3576.57 ccw(c-1384.42,3591.32) -1373.99,3580.88 -1357.41,3597.47 cw(c-1308.25,3548.3) -1308.25,3617.83 -1098.09,3617.83 C10.2@-1085.16,3630.76
VCO1-1_P: C7.2 PLL1.1 | length 325.7
  Top Layer - SIG1 w8: PLL1.1@-1384.47,3548.68 -1371.87,3561.28 ccw(c-1375.16,3564.57) -1370.51,3564.57 -1347.51,3587.57 cw(c-1308.25,3548.3) -1308.25,3603.83 -1097.22,3603.83 C7.2@-1085.16,3591.76
VCO1_N: C10.1 OSC1.5 R2.1 | length 354.5
  Top Layer - SIG1 w8: C10.1@-1047.36,3630.76 -1035.8,3619.2 -1036.24,3618.76 -1013.06,3618.76 R2.1@-1001.16,3630.66 -989.42,3618.92 -972.82,3618.92 -972.66,3618.76 -830.55,3618.76 -830.31,3619 -769.5,3619 OSC1.5@-726.5,3662
VCO1_P: C7.1 OSC1.4 R2.2 | length 357.9
  Top Layer - SIG1 w8: C7.1@-1047.36,3591.76 -1034.93,3604.2 -1029,3604.2 -1028.94,3604.26 -1012.56,3604.26 R2.2@-1001.16,3592.87 -989.42,3604.6 -972.82,3604.6 -972.66,3604.76 -772.24,3604.76 -772,3605 -769.5,3605 OSC1.4@-726.5,3562 OSC1.4@-730.8,3562
pads on no net: AUX1.2 B1.3 B1.4 B1.5 B1.6 B1.15 B3.3 B3.4 B3.5 B3.6 B3.15 BB1.6 BB1.7 BB1.8 BB1.9 BB1.10 BB2.1 BB2.2 BB2.3 BB2.4 BB2.5 BB2.6 BB2.7 BB2.8 BB2.9 BB2.10 BB3.1 BB3.2 BB3.3 BB3.4 BB3.5 BB3.6 BB3.7 BB3.8 BB3.9 BB3.10 BB4.1 BB4.2 BB4.3 BB4.4 BB5.6 BB5.7 BB5.8 BB5.9 BB6.6 BB6.7 BB6.8 BB6.9 BB6.10 BB7.1 BB7.2 BB7.3 BB7.4 BB7.5 BB8.1 BB8.2 BB8.3 BB8.4 BB8.5 BB8.6 BB8.7 BB8.8 BB8.9 BB8.10 BB9.1 BB9.2 BB9.3 BB9.4 BB9.5 BB9.6 BB9.7 BB9.8 BB9.9 BB9.10 BB10.1 BB10.2 BB10.3 BB10.4 BB10.5 BB11.6 BB11.7 BB11.8 BB11.9 BB11.10 BC1.2 BC1.3 BC1.4 BC1.5 BC1.6 BC1.10 BC1.11 BC1.24 BC1.29 BC1.30 BC1.31 BC2.2 BC2.3 BC2.4 BC2.5 BC2.6 BC2.10 BC2.11 BC2.24 BC2.29 BC2.30 BC2.31 BC3.2 BC3.3 BC3.4 BC3.5 BC3.6 BC3.10 BC3.11 BC3.24 BC3.29 BC3.30 BC3.31 BC4.2 BC4.3 BC4.4 BC4.5 BC4.6 BC4.10 BC4.11 BC4.24 BC4.29 BC4.30 BC4.31 BC5.2 BC5.3 BC5.4 BC5.5 BC5.6 BC5.10 BC5.11 BC5.24 BC5.29 BC5.30 BC5.31 BC6.9 FF1.5 FF3.1 FF3.4 FF3.6 FO1.5 FO1.10 FO1.11 FO2.3 J2.23 J2.24 J12.23 J12.24 OSC1.2 PLL1.9 PLL1.10 POT1.3 RAWPWR1.1 RAWPWR1.2 RAWPWR1.3 RAWPWR1.4 SR2.9 SR4.9 U4.1 U6.3 U7.1 U7.12 U7.14

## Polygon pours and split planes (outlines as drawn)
GND on Top Layer - SIG1 "Top Layer - SIG1-GND 1" (solid, pour order 182): -3601.84,1461 -3586.16,1456.24 -3571.71,1448.51 -3569.62,1446.8 -3499.75,1446.8 -3493.94,1447.18 -3492.95,1447.39 -3490.11,1447.44 -3489.33,1447.49 -3483.67,1448.04 -3460.05,1448.04 -3443.74,1446.44 -3428.06,1441.68 -3413.6,1433.95 -3400.94,1423.56 -3390.54,1410.89 -3382.81,1396.43 -3378.06,1380.75 -3376.45,1364.44 -3376.45,1339.24 -3378.06,1322.93 -3382.81,1307.25 -3390.54,1292.8 -3400.94,1280.13 -3413.6,1269.73 -3428.06,1262.01 -3443.74,1257.25 -3460.05,1255.64 -3483.67,1255.64 -3489.71,1256.24 -3492.8,1256.27 -3495.14,1256.77 -3499.98,1257.25 -3506.02,1259.08 -3506.6,1259.2 -3569.62,1259.2 -3571.71,1257.49 -3586.16,1249.76 -3601.84,1245 -3618.15,1243.4 -3666.15,1243.4 -3682.46,1245 -3698.15,1249.76 -3712.6,1257.49 -3725.27,1267.88 -3735.67,1280.55 -3743.39,1295.01 -3748.15,1310.69 -3749.76,1327 -3749.76,1379 -3748.15,1395.31 -3743.39,1410.99 -3735.67,1425.45 -3725.27,1438.12 -3712.6,1448.51 -3698.15,1456.24 -3682.46,1461 -3666.15,1462.6 -3618.15,1462.6
GND on Top Layer - SIG1 "Top Layer - SIG1-GND 2" (solid, pour order 180): -2697.49,1447.74 -2682.18,1443.1 -2668.08,1435.56 -2655.71,1425.41 -2645.56,1413.05 -2638.02,1398.94 -2633.38,1383.63 -2631.81,1367.72 -2631.81,1332.28 -2633.38,1316.37 -2638.02,1301.06 -2645.56,1286.95 -2655.71,1274.59 -2668.08,1264.44 -2682.18,1256.9 -2697.49,1252.26 -2713.41,1250.69 -2752.78,1250.69 -2768.69,1252.26 -2784,1256.9 -2791.69,1261.01 -3400.43,1261.01 -3406.34,1259.22 -3410.52,1258.81 -3412.42,1258.38 -3415.64,1258.3 -3422.26,1257.65 -3445.88,1257.65 -3461.8,1259.22 -3477.1,1263.86 -3491.21,1271.4 -3503.57,1281.55 -3513.72,1293.91 -3521.26,1308.02 -3525.9,1323.33 -3527.47,1339.24 -3527.47,1364.44 -3525.9,1380.36 -3521.26,1395.67 -3513.72,1409.77 -3503.57,1422.14 -3491.21,1432.28 -3477.1,1439.82 -3461.8,1444.47 -3445.88,1446.03 -3422.26,1446.03 -3415.04,1445.32 -3411.7,1445.21 -3410.09,1444.84 -3406.34,1444.47 -3400.02,1442.55 -2785.02,1442.55 -2784,1443.1 -2776.08,1445.5 -2773.2,1446.56 -2771.93,1446.76 -2768.69,1447.74 -2760.74,1448.52 -2757.4,1449.05 -2755.98,1448.99 -2752.78,1449.31 -2713.41,1449.31
GND on Top Layer - SIG1 "Top Layer - SIG1-GND 4" (solid, pour order 178): 168 vertices, not listed, extent -2582.44,1016.15 -83.15,1283.85
GND on Top Layer - SIG1 "Top Layer - SIG1-GND 6" (solid, pour order 176): -595.91,4042.47 -580.23,4037.71 -572.52,4033.59 -542.74,4033.59 -536.76,4035.41 -520.45,4037.01 -496.83,4037.01 -480.52,4035.41 -464.83,4030.65 -450.38,4022.92 -437.71,4012.53 -427.31,3999.86 -419.59,3985.4 -414.83,3969.72 -413.22,3953.41 -413.22,3928.21 -414.83,3911.9 -419.59,3896.22 -427.31,3881.77 -437.71,3869.1 -450.38,3858.7 -464.83,3850.97 -480.52,3846.22 -496.83,3844.61 -520.45,3844.61 -536.76,3846.22 -542.74,3848.03 -576.11,3848.03 -580.23,3845.83 -595.91,3841.07 -612.22,3839.47 -639.78,3839.47 -656.09,3841.07 -671.77,3845.83 -672.5,3846.22 -888,3846.22 -899.49,3847.35 -899.67,3847.36 -900.43,3847.44 -904.31,3847.83 -905.21,3848.01 -921.31,3849.9 -946,3849.9 -962.31,3851.5 -977.99,3856.26 -992.45,3863.99 -1005.12,3874.38 -1015.51,3887.05 -1023.24,3901.51 -1028,3917.19 -1029.6,3933.5 -1029.6,3944.5 -1028,3960.81 -1023.24,3976.49 -1015.51,3990.95 -1005.12,4003.62 -992.45,4014.01 -977.99,4021.74 -962.31,4026.5 -946,4028.1 -922.51,4028.1 -904.36,4030.16 -904.31,4030.17 -904.03,4030.2 -899.34,4030.73 -898.5,4030.74 -888,4031.78 -682.87,4031.78 -671.77,4037.71 -656.09,4042.47 -639.78,4044.07 -612.22,4044.07
GND on Top Layer - SIG1 "Top Layer - SIG1-GND 3" (solid, pour order 154): 154 vertices, not listed, extent -566.26,3806.14 -122.15,4073.86
NetF0_1 on Top Layer - SIG1 "Top Layer-GND_1" (solid, pour order 82): -8439.89,3222.08 -8410.53,3251.45 -7916.27,3251.45 -7864.99,3200.17 -7864.99,3030.92 -7915.76,2980.15 -8365.6,2980.15 -8439.89,3054.44
GND on Top Layer - SIG1 "L1-GND" (solid, remove dead copper, pour order 122): -9491.14,7199.89 -999.76,7199.89 -999.76,5099.89 0.24,5099.89 0.24,-0.11 -9491.14,-0.11
NetF0_1 on Bottom Layer - SIG2 "Top Layer-GND_1" (solid, pour order 130): -8440.47,3221.37 -8411.11,3250.73 -7916.85,3250.73 -7865.57,3199.45 -7865.57,3030.21 -7916.33,2979.44 -8366.18,2979.44 -8440.47,3053.73
GND on Bottom Layer - SIG2 "L6-GND" (solid, remove dead copper, pour order 124): -9491.14,7199.89 -999.76,7199.89 -999.76,5099.89 0.24,5099.89 0.24,-0.11 -9491.14,-0.11
+5V on Bottom Layer - SIG2 "Top Layer-GND_1" (solid, pour order 6): -826.42,3361.83 ccw(c-829.83,3379) -817.25,3366.83 -817.25,3461.48 -943.18,3461.48 ccw(c-943.18,3361.49) -1013.89,3432.19 -1028.25,3417.83 -1086.96,3359.12 ccw(c-1016.26,3288.41) -1116.25,3288.41 -1116.25,3184.83 -1017.05,3184.83 ccw(c-1017.05,3232.63) -983.25,3198.83 -983.25,3245.83 ccw(c-985.65,3245.83) -983.96,3247.54 -998.25,3261.83 -998.25,3315.83 -981.54,3332.54 cw(c-910.83,3261.83) -910.83,3361.83
NetD8_2 on Bottom Layer - SIG2 "Top Layer-GND_1" (solid, pour order 68): -745.2,3206.92 -688,3206.92 -659.43,3247.79 -663,3451 -716,3451 -714,3366 -733.68,3341.44 -733.68,3241
-5V on Bottom Layer - SIG2 "Top Layer-GND_1" (solid, pour order 70): -1135.25,3157.83 -1006.25,3157.83 -1006.25,3101.83 -1020.25,3101.83 -1019.25,3101.83 -1019.25,3022.83 -1019.25,2981.83 -1073.25,2981.83 -1146.25,2981.83 -1146.25,2991.83 -1146.25,3065.83 -1135.25,3065.83
NetC125_1 on Bottom Layer - SIG2 "Top Layer-GND_1" (solid, pour order 76): -976.25,3310.83 -976.25,3200.83 -976.25,3204.83 -863.48,3204.83 -863.48,3309.83 -864.25,3309.83 -972.25,3309.83 -972.25,3312.83
GND on Layer 2 - GND1 (split plane): -1020.57,7179.37 -1020.57,5098.53 -1020.19,5094.61 -1019.04,5090.84 -1017.19,5087.37 -1014.69,5084.32 -1011.64,5081.82 -1008.17,5079.97 -1004.4,5078.82 -1000.48,5078.44 -20.12,5078.44 -20.1,20.1 -8716.11,19.88 -8714.77,2979.65 -8714.77,2979.66 -8714.96,2981.61 -8715.15,2983.58 -8715.72,2985.47 -8716.29,2987.35 -8716.3,2987.35 -8716.46,2987.67 -8716.48,2988 -8717.5,2994.9 -8719.2,3001.67 -8721.55,3008.24 -8724.53,3014.55 -8728.12,3020.53 -8732.28,3026.14 -8736.96,3031.31 -8742.14,3036 -8747.74,3040.16 -8753.73,3043.74 -8760.04,3046.73 -8766.61,3049.08 -8773.38,3050.77 -8780.28,3051.8 -8787.06,3052.13 -8787.25,3052.15 -8787.26,3052.15 -8787.27,3052.15 -9472.66,3051.48 -9473.15,7179.37
JTAG_3V3 on Layer 3 - PWR1 (split plane): -1664.09,5297 -1663.74,5294.39 -1662.74,5291.96 -1661.13,5289.87 -1659.04,5288.27 -1656.61,5287.26 -1654,5286.91 -1020.57,5286.91 -1020.57,5098.53 -1020.19,5094.61 -1019.04,5090.84 -1017.19,5087.37 -1014.69,5084.32 -1011.64,5081.82 -1008.17,5079.97 -1004.4,5078.82 -1000.48,5078.44 -20.12,5078.44 -20.11,4335.09 -2651.91,4335.09 -2651.91,4795.91 -2652.26,4798.52 -2653.26,4800.96 -2654.56,4802.65 -2654.26,4803.39 -2653.91,4806 -2654.26,4808.61 -2655.26,4811.04 -2656.87,4813.13 -2658.96,4814.73 -2661.39,4815.74 -2664,4816.09 -5557.91,4816.09 -5557.91,5475.82 -5552.74,5481 -2657.91,5481 -2655.3,5481.34 -2652.87,5482.35 -2652.14,5482.91 -1664.09,5482.91
RF_3V3 on Layer 3 - PWR1 (split plane): -2673.74,4793.3 -2672.74,4790.87 -2672.09,4790.03 -2672.09,4325 -2671.74,4322.39 -2670.74,4319.96 -2669.13,4317.87 -2667.04,4316.27 -2664.61,4315.26 -2662,4314.91 -20.11,4314.91 -20.11,3536.09 -1146,3536.09 -1148.61,3535.74 -1151.04,3534.73 -1153.13,3533.13 -1154.74,3531.04 -1155.74,3528.61 -1156.09,3526 -1156.09,3331.09 -1845.91,3331.09 -1845.91,3886 -1846.26,3888.61 -1847.26,3891.04 -1848.87,3893.13 -1850.96,3894.73 -1853.39,3895.74 -1856,3896.09 -4041,3896.09 -4043.61,3895.74 -4046.04,3894.73 -4048.13,3893.13 -4049.74,3891.04 -4050.74,3888.61 -4051.09,3886 -4051.09,3434.09 -5565.91,3434.09 -5565.91,4179.83 -5565.87,4179.87 -5564.26,4181.96 -5563.26,4184.39 -5562.91,4187 -5562.91,4795.91 -2674.09,4795.91
DIS3V3 on Layer 3 - PWR1 (split plane): -1020.57,5307.09 -1643.91,5307.09 -1643.91,5493 -1644.26,5495.61 -1645.26,5498.04 -1646.87,5500.13 -1648.96,5501.73 -1651.39,5502.74 -1654,5503.09 -2657.91,5503.09 -2657.91,6031.91 -1020.57,6031.91
RM_3V3 on Layer 3 - PWR1 (split plane): -1866.09,3321 -1865.74,3318.39 -1864.74,3315.96 -1863.13,3313.87 -1861.04,3312.27 -1858.61,3311.26 -1856,3310.91 -228.09,3310.91 -228.09,3085.83 -1135.25,3085.83 -1137.86,3085.49 -1140.29,3084.48 -1142.38,3082.88 -1143.98,3080.79 -1144.99,3078.36 -1145.33,3075.75 -1144.99,3073.14 -1143.98,3070.7 -1143.96,3070.68 -1144.09,3069.75 -1144.09,2724.2 -1144.74,2722.61 -1145.09,2720 -1144.74,2717.39 -1144.09,2715.8 -1144.09,2711 -1143.74,2708.39 -1142.74,2705.96 -1142.09,2705.11 -1142.09,2276.09 -1918.91,2276.09 -1918.91,2440 -1919.26,2442.61 -1920.26,2445.04 -1921.87,2447.13 -1923.96,2448.74 -1926.39,2449.74 -1929,2450.09 -2471.82,2450.09 -3448.24,3426.51 -3448.26,3426.61 -3449.26,3429.04 -3450.87,3431.13 -3452.96,3432.73 -3455.39,3433.74 -3458,3434.09 -4030.91,3434.09 -4030.91,3875.91 -1866.09,3875.91
+5V on Layer 3 - PWR1 (split plane): -20.1,20.1 -708.91,20.08 -708.91,895 -218,895 -215.39,895.35 -212.96,896.35 -210.87,897.96 -209.26,900.05 -208.26,902.48 -207.91,905.09 -207.91,3321 -208.26,3323.61 -209.26,3326.04 -210.87,3328.13 -212.96,3329.73 -215.39,3330.74 -218,3331.09 -1135.91,3331.09 -1135.91,3515.91 -20.11,3515.91
-5V on Layer 3 - PWR1 (split plane): -228.09,915.18 -719,915.18 -721.61,914.83 -724.04,913.82 -726.13,912.22 -727.74,910.13 -728.74,907.7 -729.09,905.09 -729.09,20.08 -828.91,20.08 -828.91,1022.43 -490,1022.43 -487.39,1022.77 -484.96,1023.78 -482.87,1025.38 -481.26,1027.47 -480.26,1029.91 -479.91,1032.52 -479.91,2711 -480.26,2713.61 -481.26,2716.04 -482.87,2718.13 -484.96,2719.73 -487.39,2720.74 -490,2721.09 -1122.06,2721.09 -1122.26,2722.61 -1123.26,2725.04 -1123.91,2725.89 -1123.91,3065.66 -228.09,3065.66
BMA_3V3 on Layer 3 - PWR1 (split plane): -2483.13,2432.87 -2481.04,2431.26 -2479.32,2430.55 -2478.61,2430.26 -2476,2429.91 -1939.09,2429.91 -1939.09,2266 -1938.74,2263.39 -1937.74,2260.96 -1936.13,2258.87 -1934.04,2257.26 -1931.61,2256.26 -1929,2255.91 -1363.09,2255.91 -1363.09,2123.18 -1495.18,1991.09 -2354.82,1991.09 -2493.87,2130.13 -2495.96,2131.74 -2498.39,2132.74 -2501,2133.09 -3185.82,2133.09 -3583.87,2531.13 -3585.96,2532.73 -3587.19,2533.24 -3587.87,2534.13 -3589.96,2535.73 -3592.39,2536.74 -3595,2537.09 -5566.03,2537.09 -5565.91,2538 -5565.91,3413.91 -3464.18,3413.91
BMB_3V3 on Layer 3 - PWR1 (split plane): -500.09,1698.09 -5568.91,1698.09 -5568.91,2516.91 -3598.17,2516.91 -3598.13,2516.87 -3197.13,2115.87 -3195.04,2114.26 -3192.61,2113.26 -3190,2112.91 -2505.18,2112.91 -2366.13,1973.87 -2364.04,1972.26 -2362.32,1971.55 -2361.61,1971.26 -2359,1970.91 -1491,1970.91 -1488.39,1971.26 -1485.96,1972.26 -1483.87,1973.87 -1345.87,2111.87 -1344.26,2113.96 -1343.26,2116.39 -1342.91,2119 -1342.91,2255.91 -1132,2255.91 -1129.39,2256.26 -1126.96,2257.26 -1124.87,2258.87 -1123.26,2260.96 -1122.26,2263.39 -1121.91,2266 -1121.91,2700.91 -500.09,2700.91
5VAUX on Layer 3 - PWR1 (split plane): -3642.09,987.09 -5163.91,987.09 -5163.91,1121 -5164.26,1123.61 -5165.26,1126.04 -5166.87,1128.13 -5168.96,1129.74 -5171.39,1130.74 -5174,1131.09 -5569.91,1131.09 -5569.91,1677.91 -3642.09,1677.91
3V3AUX on Layer 3 - PWR1 (split plane): -500.09,1042.6 -839,1042.6 -841.61,1042.26 -844.04,1041.25 -846.13,1039.65 -847.74,1037.56 -848.74,1035.13 -849.09,1032.52 -849.09,20.08 -5570.91,19.96 -5570.91,1110.91 -5184.09,1110.91 -5184.09,977 -5183.74,974.39 -5182.74,971.96 -5181.13,969.87 -5179.04,968.26 -5176.61,967.26 -5174,966.91 -3632,966.91 -3629.39,967.26 -3626.96,968.26 -3624.87,969.87 -3623.26,971.96 -3622.26,974.39 -3621.91,977 -3621.91,1677.91 -500.09,1677.91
